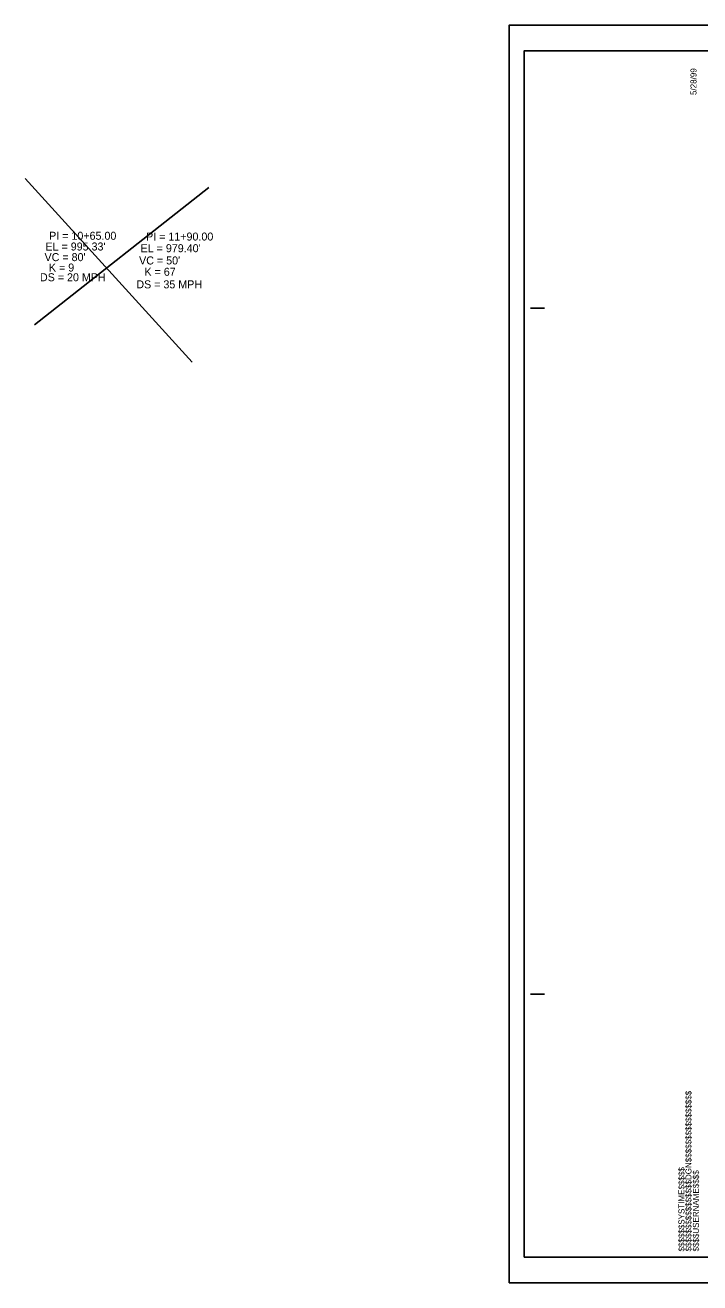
# Model space of a CAD drawing. Extents: x 1628636 to 1631253, y 896159 to 897520.
# Drawn here: x 1628636 to 1629226, y 896159 to 897259 of the extents above; entities that cross this region are included whole.
import ezdxf

# ---------------------------------------------------------------- set-up
doc = ezdxf.new("R2010")
doc.units = 0
for name, color, linetype in [('Prop Vertical Profile Curve Label', 7, 'Continuous'), ('Prop VPI Label', 7, 'Continuous'), ('Scratch_Level_6', 7, 'Continuous'), ('Sheet Cutting Line CELL', 7, 'Continuous'), ('Sheet Plot Border Inside CELL', 7, 'Continuous'), ('Sheet Plot Border Outside CELL', 7, 'Continuous'), ('Sheet Profile CELL', 7, 'Continuous')]:
    doc.layers.add(name, color=color, linetype=linetype)

msp = doc.modelspace()

# ---------------------------------------------------------------- linework, layer by layer
at = {"layer": 'Scratch_Level_6'}
for p, q in [((1628782.1, 896964.2), (1628636.2, 897124.9)), ((1628644.3, 896996.7), (1628796.7, 897116.8))]:
    msp.add_line(p, q, dxfattribs=at)
at = {"layer": 'Sheet Cutting Line CELL'}
for p, q in [((1630743.5, 897258.9), (1629059.5, 897258.9)), ((1629059.5, 897258.9), (1629059.5, 896158.9)), ((1629059.5, 896158.9), (1630743.5, 896158.9))]:
    msp.add_line(p, q, dxfattribs=at)
at = {"layer": 'Sheet Plot Border Inside CELL'}
msp.add_lwpolyline([(1629072.5, 896181.3), (1630739, 896181.3), (1630739, 897236.4), (1629072.5, 897236.4)], close=True, dxfattribs=at)
at = {"layer": 'Sheet Plot Border Outside CELL'}
msp.add_lwpolyline([(1629059.5, 896158.9), (1630743.5, 896158.9), (1630743.5, 897258.9), (1629059.5, 897258.9)], close=True, dxfattribs=at)
at = {"layer": 'Sheet Profile CELL'}
for p, q in [((1629078, 897011.4), (1629090.5, 897011.4)), ((1629078, 896411.4), (1629090.5, 896411.4))]:
    msp.add_line(p, q, dxfattribs=at)

# ---------------------------------------------------------------- texts
at = {"layer": 'Prop Vertical Profile Curve Label'}
for s, p in [("VC = 80'", (1628653.1, 897052.5)), ('K = 9', (1628656.9, 897043.4)), ("VC = 50'", (1628735.8, 897049.6)), ('K = 67', (1628740.5, 897039.7))]:
    msp.add_text(s, height=7, dxfattribs=at).set_placement(p)
at = {"layer": 'Prop VPI Label'}
for s, p in [('PI = 10+65.00', (1628657.1, 897071.2)), ('PI = 11+90.00', (1628741.9, 897070.5)), ("EL = 995.33'", (1628653.9, 897061.8)), ("EL = 979.40'", (1628737.1, 897060.3)), ('DS = 20 MPH', (1628649.1, 897034.9)), ('DS = 35 MPH', (1628733.4, 897028.7))]:
    msp.add_text(s, height=7, dxfattribs=at).set_placement(p)
at = {"layer": 'Sheet Profile CELL'}
for s, p in [('5/28/99', (1629223.3, 897197.8)), ('$$$$$$$$$$$$$$$$DGN$$$$$$$$$$$$$$$$', (1629218.9, 896186.3)), ('$$$$$$SYSTIME$$$$$', (1629212.8, 896186.3)), ('$$$$USERNAME$$$$', (1629225.4, 896186.3))]:
    msp.add_text(s, height=5.25, rotation=90, dxfattribs=at).set_placement(p)

doc.saveas('drawing.dxf')
